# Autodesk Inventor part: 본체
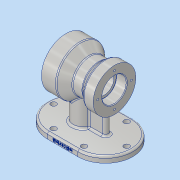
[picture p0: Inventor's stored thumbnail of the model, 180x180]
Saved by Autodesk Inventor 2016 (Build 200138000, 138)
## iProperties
Created: 2020-01
Part Number: 본체
Material: 알루미늄 6061
Document SubType Name: Modeling
Designer: woori
Density: 2.7 g/cm^3
Appearance: 알루미늄 - 평지
Mass: 934.233 g
Surface Area: 654.734 cm^2
Volume: 346.012 cm^3
Author: woori
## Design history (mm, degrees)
sketch "스케치3"
  geometry: L1 (-70, 0)-(-25, 0); L2 (-25, 0)-(25, 0); L3 (25, 0)-(70, 0); L4 (-70, 0)-(-70, 10); L5 (-70, 10)-(70, 10); L6 (70, 10)-(70, 0); 2 further points
  constraints: 12 end point, 2 perpendicular, 2 point on line, 1 coincident, 1 horizontal, 1 midpoint, 1 vertical
  dimensions: "d10" = 45 distance of L1.start L1.end; "d11" = 50 distance of L1.end L2.end; "d12" = 45 distance of L2.end L3.end; "d13" = 10 distance of L1.start L4.end
extrude "돌출1" new body sketch "스케치3" stored distance "d14" = 90; taper "d15" = 0 deg
fillet "모깎기1" dims "d16" = 45
sketch "스케치4"
  geometry: L1 (-40, 80)-(143.887, 80); L2 (-40, 80)-(-40, 120); L3 (-40, 120)-(-16, 120); L4 (40, 115)-(40, 80); L5 (24, 115)-(40, 115); L6 (40, 115)-(40, 80); L7 (-40, 120)-(-16, 120); L8 (-61.291, 80)-(69.038, 80); L9 (-16, 120)-(-1.103, 107.5); L10 (-16, 120)-(3.447, 120); L11 (24, 115)-(44.887, 115); L12 (24, 115)-(15.062, 107.5); L13 (-1.103, 107.5)-(15.062, 107.5); L14 (-25, 0)-(-25, 0) reference; L15 (-25, 0)-(-25, 10) reference; L16 (-25, 10)-(-25, 10) reference; L17 (-25, 10)-(-25, 0) reference; L18 (-70, 10)-(-70, 0) reference; L19 (-70, 10)-(-70, 0) reference; L20 (-70, 10)-(-70, 0) reference; L21 (-25, 0)-(25, 0) reference; 1 further point
  constraints: 26 end point, 4 horizontal, 2 point on line, 1 equal length, 1 parallel, 1 vertical
  dimensions: "d22" = 24 distance of L3.end L2.end; "d25" = 40 deg angle of L9 L10; "d27" = 140 deg angle of L13 L12; "d31" = 30 distance between parallel lines of L18 L2; "d32" = 80 distance between parallel lines of L21 L1; "d33" = 80 distance between parallel lines of L4 L2; "d34" = 16 distance of L5.start L4.start; "d35" = 55 diameter of L13 L1; "d37" = 70 diameter of L5 L1; "d38" = 80 diameter of L3 L1
revolve "회전1" sketch "스케치4" stored, may be unused: angle "d29" = 90 deg
sketch "스케치5"
  geometry: L1 (-49.461, 80)-(59.544, 80); L2 (-40, 40)-(-40, 120) reference; L3 (-40, 80)-(-20, 80); L4 (-20, 80)-(-20, 106); L5 (-20, 106)-(-40, 106); L6 (-40, 106)-(-40, 80); L7 (-20, 80)-(23, 80); L8 (23, 80)-(23, 96); L9 (23, 96)-(-20, 96); L10 (-20, 96)-(-20, 80); L11 (40, 45)-(40, 115) reference; L12 (40, 80)-(23, 80); L13 (23, 80)-(23, 100); L14 (23, 100)-(40, 100); L15 (40, 100)-(40, 80); L16 (-40, 120)-(-16, 120) reference; L17 (-40, 40)-(-16, 40) reference; L18 (24, 115)-(40, 115) reference; L19 (24, 45)-(40, 45) reference; L20 (70, 0)-(25, 0) reference; 1 further point
  constraints: 26 end point, 6 parallel, 4 horizontal, 3 perpendicular, 2 midpoint, 1 point on line
  dimensions: "d39" = 20 distance of L5.end L4.end; "d41" = 52 diameter of L5 L1; "d43" = 17 distance of L13.end L14.end; "d45" = 40 diameter of L14 L1; "d46" = 32 diameter of L9 L1; "d47" = 80 distance between parallel lines of L20 L1
revolve "회전2" sketch "스케치5" stored, may be unused: angle "d48" = 90 deg
chamfer "모따기1" distance "d49" = 1; stored, may be unused: second distance "d50" = 2, angle "d51" = 45 deg
chamfer "모따기2" distance "d52" = 1; stored, may be unused: second distance "d53" = 2, angle "d54" = 45 deg
fillet "모깎기2" dims "d55" = 0.3
fillet "모깎기3" dims "d56" = 0.3
sketch "스케치6" dims "d57" = 66
  geometry: L1 (45, -80)-(-45, -80) reference; 3 further points
  constraints: 3 vertical alignment, 2 other
  dimensions: "d58" = 80 distance from line of L1 point (0, 0)
hole "구멍1" sketch "스케치6" at (0, 33) diameter "d59" = 3.242; stored, may be unused: countersink angle "d63" = 90 deg, drill point angle "d65" = 118 deg; dims "d60" = 9, "d61" = 4, "d62" = 2, "d64" = 11
sketch "스케치7" dims "d69" = 55
  geometry: L1 (45, -80)-(-45, -80) reference; 4 further points
  constraints: 3 vertical alignment, 1 midpoint, 2 other
  dimensions: "d70" = 80 distance from line of L1 point (0, 0)
hole "구멍2" sketch "스케치7" at (0, 27.5) diameter "d71" = 3.242; stored, may be unused: countersink angle "d75" = 90 deg, drill point angle "d77" = 118 deg; dims "d72" = 9, "d73" = 4, "d74" = 2, "d76" = 11
sketch "스케치8"
  geometry: L1 (50, 45)-(25.196, 45); L2 (50, 50)-(25.196, 50); L3 (25.196, 40)-(50, 40); C1 r 16 at (13, 45); A1 r 45 centre (0, 45) between (0, 90) and (0, 0) reference; A2 r 5 centre (50, 45) between (50, 40) and (50, 50); A3 r 5 centre (25.196, 45) between (25.196, 50) and (25.196, 40); 3 further points
  constraints: 8 end point, 5 point on circle, 4 tangent, 3 centre point, 2 horizontal alignment, 1 horizontal, 1 midpoint, 1 parallel
  dimensions: "d81" = 32 diameter of C1; "d82" = 58 distance of C1.centre point (-45, 45); "d83" = 50 distance of L1.start A1.centre; "d84" = 10 distance between parallel lines of L3 L2
extrude "돌출2" join sketch "스케치8" stored distance "d85" = 90; taper "d86" = 0 deg
fillet "모깎기4" dims "d87" = 3
fillet "모깎기5" dims "d88" = 3
fillet "모깎기6" dims "d89" = 3
sketch "스케치9"
  geometry: L1 (50, -77)-(0, -77); L2 (50, -7)-(0, -7); A1 r 45 centre (50, -42) between (50, -87) and (50, 3) reference; A2 r 35 centre (50, -42) between (50, -7) and (50, -77); A3 r 35 centre (0, -42) between (0, -77) and (0, -7); 6 further points
  constraints: 6 point on circle, 4 coincident, 4 end point, 2 centre point, 2 tangent
  dimensions: "d90" = 70 diameter of A2; "d91" = 70 diameter of A3; "d92" = 50 distance of A3.centre A2.centre
hole "구멍3" sketch "스케치9" at (50, -7), (50, -77), (0, -77), (85, -42), (0, -7), (-35, -42) diameter "d93" = 9; stored, may be unused: countersink angle "d97" = 90 deg, drill point angle "d99" = 118 deg; dims "d94" = 9, "d95" = 4, "d96" = 2, "d98" = 11
sketch "스케치10"
  geometry: L1 (-70, 7)-(-70, 0) reference; L2 (70, 0)-(25, 0) reference; 2 further points
  constraints: 1 other
  dimensions: "d100" = 70 distance from line of point (0, 4) L1; "d101" = 4 distance from line of L2 point (0, 4)
feature "엠보싱1" sketch "스케치10" dims "d10" = 45, "d11" = 50, "d12" = 45, "d13" = 10, "d22" = 24, "d25" = 40 deg, "d27" = 140 deg, "d31" = 30, "d32" = 80, "d33" = 80, "d34" = 16, "d35" = 55, "d37" = 70, "d38" = 80, "d102" = 0.5, "d103" = 0
node "솔리드1"
pattern_circular "원형 패턴1" dims angle "d67" = 360 deg
pattern_circular "원형 패턴2" dims angle "d79" = 360 deg
node "투영된 루프1"
other parameters: "d24" = 27.5
